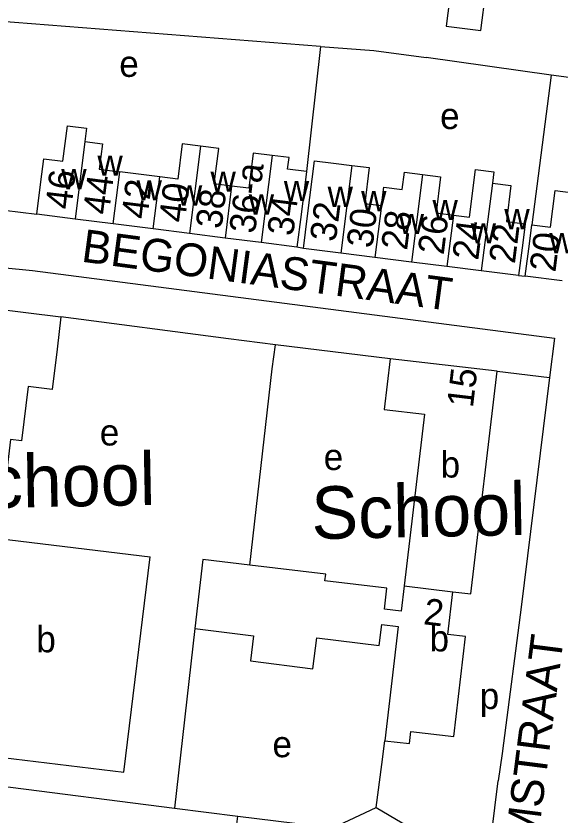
# Model space of a CAD drawing. Extents: x 161258 to 163262, y 380749 to 382054.
# Drawn here: x 162145.4 to 162228.4, y 381307.3 to 381429.2 of the extents above; entities that cross this region are included whole.
import ezdxf

# ---------------------------------------------------------------- set-up
doc = ezdxf.new("R2010")
doc.units = 0
for name, color, linetype in [('BLT_Basislijn', 7, 'Continuous'), ('BLT_Bebouwing', 7, 'Continuous'), ('BLT_Bebouwing_beschrifting', 7, 'Continuous'), ('BLT_Centroide', 7, 'Continuous'), ('BLT_Huisnummer', 7, 'Continuous'), ('BLT_Huisnummer_ tussenligend', 7, 'Continuous'), ('BLT_Huisnummer_reeks', 7, 'Continuous'), ('BLT_Onderverdeling_panden', 7, 'Continuous'), ('BLT_Straatnaam', 7, 'Continuous')]:
    doc.layers.add(name, color=color, linetype=linetype)

msp = doc.modelspace()

# ---------------------------------------------------------------- linework, layer by layer
at = {"layer": 'BLT_Basislijn'}
for p, q in [((162191.84, 381424.6), (162132.95, 381429.2)), ((162191.84, 381424.6), (162189.71, 381405.54)), ((162227.04, 381420.22), (162208.01, 381422.89)), ((162227.04, 381420.22), (162224.09, 381397.41)), ((162242.48, 381418.18), (162227.04, 381420.22)), ((162143.62, 381399.63), (162148.58, 381399.01)), ((162189.26, 381393.81), (162188.26, 381394.02)), ((162222.09, 381389.68), (162223.1, 381389.56)), ((162202.49, 381377), (162185, 381379.14)), ((162218.8, 381375.08), (162226.81, 381374.13)), ((162172.69, 381335.86), (162169.61, 381308.51)), ((162201.21, 381315.16), (162201.68, 381318.77)), ((162200.34, 381308.58), (162201.21, 381315.16)), ((162124.92, 381314.14), (162169.61, 381308.51)), ((162217.69, 381302.26), (162218.96, 381312.68)), ((162169.61, 381308.51), (162179.26, 381307.29)), ((162178.03, 381297.58), (162179.26, 381307.29))]:
    msp.add_line(p, q, dxfattribs=at)
for points in [[(162191.84, 381424.6), (162200.02, 381423.96), (162208.01, 381422.89)], [(162122.23, 381325.29), (162129.94, 381388.31), (162130.8, 381390.09), (162132.51, 381391.45), (162134.99, 381391.72), (162147.9, 381390.45), (162227.56, 381380.14), (162226.81, 381374.13)], [(162185, 381379.14), (162177.83, 381380.01), (162152.27, 381383.4)], [(162181.1, 381345.55), (162184.48, 381375.48), (162185, 381379.14)], [(162226.81, 381374.13), (162222.49, 381339.11), (162219.77, 381318.38)], [(162219.77, 381318.38), (162219.56, 381316.84), (162218.96, 381312.68)], [(162179.26, 381307.29), (162193.74, 381305.47), (162200.34, 381308.58)], [(162200.34, 381308.58), (162209.17, 381303.41), (162209.83, 381303.32)]]:
    msp.add_lwpolyline(points, dxfattribs=at)
at = {"layer": 'BLT_Bebouwing'}
for p, q in [((162167.35, 381404.7), (162161.24, 381405.47)), ((162154.42, 381398.28), (162148.58, 381399.01)), ((162160.24, 381397.54), (162154.42, 381398.28)), ((162166.35, 381396.78), (162160.24, 381397.54)), ((162171.87, 381396.08), (162166.35, 381396.78)), ((162177.3, 381395.4), (162171.87, 381396.08)), ((162182.83, 381394.7), (162177.3, 381395.4)), ((162188.26, 381394.02), (162182.83, 381394.7)), ((162194.96, 381393.09), (162189.26, 381393.81)), ((162200.17, 381392.44), (162194.96, 381393.09)), ((162205.75, 381391.74), (162200.17, 381392.44)), ((162211.16, 381391.05), (162205.75, 381391.74)), ((162216.4, 381390.4), (162211.16, 381391.05)), ((162222.09, 381389.68), (162216.4, 381390.4)), ((162228.74, 381388.85), (162223.1, 381389.56))]:
    msp.add_line(p, q, dxfattribs=at)
for points in [[(162211.55, 381431.64), (162211.03, 381427.69), (162216.35, 381427.03), (162217.08, 381432.98), (162219.76, 381432.64)], [(162148.58, 381399.01), (162149.21, 381403.97), (162149.65, 381407.46), (162152.54, 381407.1), (162153.25, 381412.49), (162156.16, 381412.15), (162155.9, 381410.09)], [(162155.9, 381410.09), (162158.58, 381409.78), (162158.08, 381405.87), (162161.24, 381405.47)], [(162173.55, 381409.38), (162170.76, 381409.73), (162170.09, 381404.36), (162167.35, 381404.7)], [(162178.3, 381403.31), (162175.65, 381403.65), (162176.33, 381409.03), (162173.55, 381409.38)], [(162184.5, 381407.98), (162181.61, 381408.34), (162180.94, 381402.98), (162178.3, 381403.31)], [(162189.71, 381405.54), (162186.84, 381405.9), (162187.06, 381407.65), (162184.5, 381407.98)], [(162189.26, 381393.81), (162189.88, 381398.77), (162190.95, 381407.18), (162193.83, 381406.81), (162196.64, 381406.46)], [(162196.64, 381406.46), (162199.3, 381406.13), (162198.61, 381400.68), (162201.16, 381400.35)], [(162189.71, 381405.54), (162188.89, 381398.98), (162188.26, 381394.02)], [(162201.16, 381400.35), (162201.51, 381403.16), (162204.34, 381402.81), (162204.67, 381405.45), (162207.43, 381405.1)], [(162212.15, 381398.9), (162214.58, 381398.59), (162215.49, 381405.82), (162218.3, 381405.48), (162218.08, 381403.74)], [(162207.43, 381405.1), (162210.19, 381404.75), (162209.5, 381399.23), (162212.15, 381398.9)], [(162218.08, 381403.74), (162220.92, 381403.39), (162220.24, 381397.94), (162223.08, 381397.58), (162222.71, 381394.64), (162222.09, 381389.68)], [(162224.09, 381397.41), (162226.97, 381397.05), (162227.67, 381402.62), (162230.43, 381402.28)], [(162223.1, 381389.56), (162223.73, 381394.52), (162224.09, 381397.41)], [(162131.13, 381340.86), (162136.6, 381385.3), (162152.27, 381383.4)], [(162152.27, 381383.4), (162151.67, 381378.44), (162150.92, 381372.29), (162147.25, 381372.74), (162146.24, 381364.5), (162144.56, 381364.71), (162142.72, 381349.6), (162165.87, 381346.79)], [(162202.49, 381377), (162201.58, 381369.28), (162207.73, 381368.56), (162204.65, 381342.39)], [(162218.8, 381375.08), (162202.49, 381377)], [(162212.07, 381341.46), (162214.8, 381341.14), (162218.8, 381375.08)], [(162131.13, 381340.86), (162136.06, 381340.24), (162133.27, 381317.45), (162161.85, 381313.96), (162165.87, 381346.79)], [(162181.1, 381345.55), (162173.93, 381346.39), (162172.69, 381335.86)], [(162192.54, 381343.13), (162192.66, 381344.18), (162181.1, 381345.55)], [(162204.65, 381342.39), (162204.19, 381338.53), (162201.62, 381338.84), (162201.99, 381342.02), (162192.54, 381343.13)], [(162212.2, 381319.41), (162213.99, 381334.64), (162211.3, 381334.96), (162212.07, 381341.46)], [(162172.69, 381335.86), (162181.64, 381334.78), (162181.16, 381330.93), (162190.68, 381329.74), (162191.29, 381334.44)], [(162191.29, 381334.44), (162200.83, 381333.29), (162201.2, 381336.46), (162203.73, 381336.16), (162201.68, 381318.77)], [(162201.68, 381318.77), (162205.43, 381318.33), (162205.64, 381320.18), (162212.2, 381319.41)]]:
    msp.add_lwpolyline(points, dxfattribs=at)
at = {"layer": 'BLT_Onderverdeling_panden'}
for p, q in [((162155.9, 381410.09), (162154.42, 381398.28)), ((162173.55, 381409.38), (162171.87, 381396.08)), ((162184.5, 381407.98), (162182.83, 381394.7)), ((162196.64, 381406.46), (162194.96, 381393.09)), ((162160.24, 381397.54), (162161.24, 381405.47)), ((162166.35, 381396.78), (162167.35, 381404.7)), ((162207.43, 381405.1), (162205.75, 381391.74)), ((162178.3, 381403.31), (162177.3, 381395.4)), ((162218.08, 381403.74), (162216.4, 381390.4)), ((162201.16, 381400.35), (162200.17, 381392.44)), ((162212.15, 381398.9), (162211.16, 381391.05)), ((162204.65, 381342.39), (162212.07, 381341.46))]:
    msp.add_line(p, q, dxfattribs=at)

# ---------------------------------------------------------------- texts
at = {"layer": 'BLT_Bebouwing_beschrifting'}
for rotation, p in [(1.0866, (162134.02, 381354.1)), (1.1433, (162190.54, 381349.49))]:
    msp.add_text('School', height=8, rotation=rotation, dxfattribs=at).set_placement(p)
at = {"layer": 'BLT_Centroide'}
for s, p in [('e', (162161.16, 381419.96)), ('e', (162210.11, 381412.01)), ('w', (162157.83, 381404.89)), ('w', (162152.31, 381402.83)), ('w', (162175.08, 381402.44)), ('w', (162163.8, 381401.12)), ('w', (162186.27, 381401.02)), ('w', (162169.95, 381400.34)), ('w', (162192.95, 381400.14)), ('w', (162180.91, 381398.97)), ('w', (162198.06, 381399.48)), ('w', (162208.95, 381398.12)), ('w', (162203.8, 381396)), ('w', (162219.91, 381396.73)), ('w', (162214.78, 381394.58)), ('w', (162226.77, 381393.08)), ('e', (162158.19, 381363.77)), ('e', (162192.35, 381360.03)), ('b', (162210.19, 381358.89)), ('b', (162148.5, 381332.25)), ('b', (162208.5, 381332.38)), ('p', (162216.16, 381323.6)), ('e', (162184.53, 381316.25))]:
    msp.add_text(s, height=4, dxfattribs=at).set_placement(p)
at = {"layer": 'BLT_Huisnummer'}
for s, rotation, p in [('46', 83.3452, (162153.84, 381399.65)), ('42', 82.8283, (162165.43, 381398.17)), ('38', 82.834, (162176.76, 381396.69)), ('34', 82.8309, (162187.68, 381395.6)), ('30', 82.8358, (162199.78, 381393.75)), ('26', 82.8363, (162210.65, 381392.74)), ('22', 82.8309, (162221.51, 381391.38)), ('15', 83.276, (162215.11, 381369.43)), ('2', 353.28, (162207.46, 381336.54))]:
    msp.add_text(s, height=4, rotation=rotation, dxfattribs=at).set_placement(p)
at = {"layer": 'BLT_Huisnummer_ tussenligend'}
for s, rotation, p in [('44', 82.8283, (162159.57, 381398.84)), ('40', 82.834, (162171.16, 381397.64)), ('32', 82.8358, (162194.19, 381394.72)), ('28', 82.8363, (162205.06, 381393.43)), ('24', 82.8309, (162215.92, 381391.91)), ('20', 82.893, (162227.7, 381390.09))]:
    msp.add_text(s, height=4, rotation=rotation, dxfattribs=at).set_placement(p)
at = {"layer": 'BLT_Huisnummer_reeks'}
msp.add_text('36-a', height=4, rotation=82.8309, dxfattribs=at).set_placement((162181.87, 381395.96))
at = {"layer": 'BLT_Straatnaam'}
for s, rotation, p in [('BEGONIASTRAAT', 352.3974, (162155.24, 381391.81)), ('GERANIUMSTRAAT', 82.7202, (162221.09, 381272.66))]:
    msp.add_text(s, height=5, rotation=rotation, dxfattribs=at).set_placement(p)

doc.saveas('drawing.dxf')
